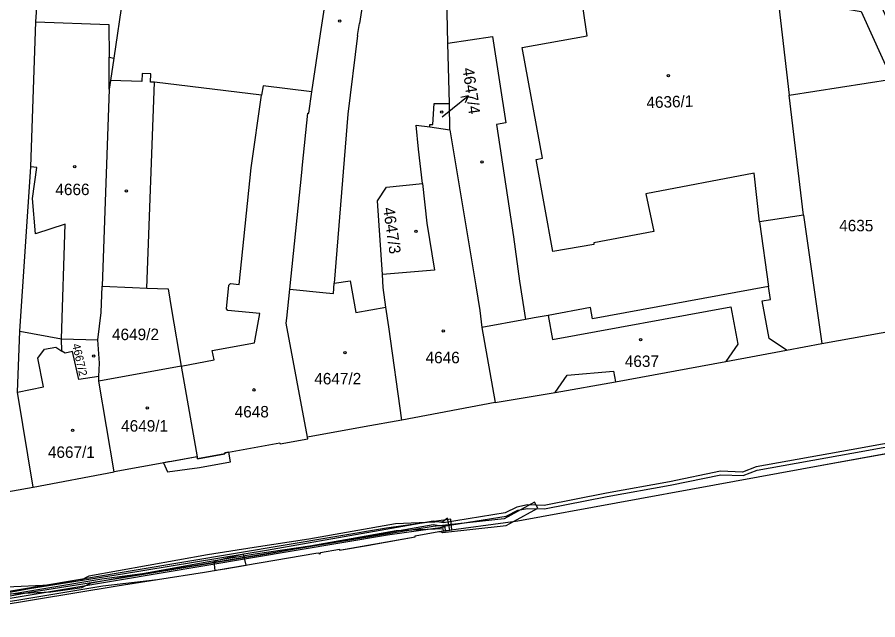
# Model space of a CAD drawing. Extents: x -756746 to -753363, y -1166406 to -1161727.
# Drawn here: x -755379 to -755251.5, y -1166104 to -1166014.7 of the extents above; entities that cross this region are included whole.
import ezdxf

# ---------------------------------------------------------------- set-up
doc = ezdxf.new("R2010")
doc.units = 0
for name, color, linetype in [('Hranice kat_území', 7, 'Continuous'), ('Hranice parcel', 7, 'Continuous'), ('Parcelní čísla', 7, 'Continuous'), ('Pop  PČ popisy', 7, 'Continuous'), ('Vnitřní kresba', 7, 'Continuous'), ('Věcná břemena k části', 7, 'Continuous'), ('Značky budov', 7, 'Continuous')]:
    doc.layers.add(name, color=color, linetype=linetype)

msp = doc.modelspace()

# ---------------------------------------------------------------- linework, layer by layer
at = {"layer": 'Hranice kat_území'}
for points in [[(-755316.54, -1166090.97), (-755304.83, -1166089.37), (-755275.71, -1166084.03), (-755259.8, -1166081.14), (-755244.88, -1166078.42)], [(-755388.47, -1166103.01), (-755364.24, -1166099.02), (-755358.23, -1166098.07), (-755351.29, -1166096.97), (-755334.76, -1166094.17), (-755334.32, -1166094.1), (-755334.29, -1166094.25), (-755334.07, -1166094.23), (-755334.1, -1166094.06), (-755331.29, -1166093.57), (-755331.26, -1166093.72), (-755320.05, -1166091.75), (-755320.08, -1166091.59), (-755316.54, -1166090.97)]]:
    msp.add_lwpolyline(points, dxfattribs=at)
at = {"layer": 'Hranice parcel'}
for p, q in [((-755376.29, -1166015.44), (-755374.69, -1165994.77)), ((-755267.71, -1165999.92), (-755264.63, -1166026.3)), ((-755364.7, -1166020.81), (-755365.2, -1166024.14)), ((-755264.63, -1166026.3), (-755249.46, -1166023.94)), ((-755262.54, -1166044.1), (-755264.63, -1166026.3)), ((-755314.91, -1166031.43), (-755315, -1166027.54)), ((-755317.9, -1166031.01), (-755314.91, -1166031.43)), ((-755262.54, -1166044.1), (-755259.81, -1166063.09)), ((-755310.49, -1166058.19), (-755310.21, -1166060.74)), ((-755303.71, -1166059.54), (-755310.21, -1166060.74)), ((-755302.45, -1166059.31), (-755303.71, -1166059.54)), ((-755259.81, -1166063.09), (-755244.79, -1166060.36)), ((-755378.64, -1166061.27), (-755372.49, -1166062.39)), ((-755310.21, -1166060.74), (-755308.23, -1166071.84)), ((-755372.49, -1166062.39), (-755367.07, -1166062.57)), ((-755354.75, -1166066.43), (-755366.95, -1166068.66)), ((-755354.75, -1166066.43), (-755352.38, -1166079.89)), ((-755366.95, -1166068.66), (-755366.93, -1166067.96)), ((-755364.64, -1166082.11), (-755366.95, -1166068.66)), ((-755308.23, -1166071.84), (-755322.06, -1166074.47)), ((-755259.8, -1166081.14), (-755244.88, -1166078.42)), ((-755352.38, -1166079.89), (-755364.64, -1166082.11)), ((-755376.64, -1166084.36), (-755364.64, -1166082.11)), ((-755275.71, -1166084.03), (-755259.8, -1166081.14)), ((-755392.01, -1166087.13), (-755376.64, -1166084.36)), ((-755304.83, -1166089.37), (-755275.71, -1166084.03)), ((-755316.54, -1166090.97), (-755304.83, -1166089.37)), ((-755351.29, -1166096.97), (-755334.76, -1166094.17))]:
    msp.add_line(p, q, dxfattribs=at)
for points in [[(-755335.36, -1166025.81), (-755334.11, -1166017.2), (-755332.76, -1166008.51), (-755330.85, -1165995.94), (-755330.23, -1165991.73), (-755328.39, -1165979.53), (-755327.36, -1165972.71)], [(-755315, -1166027.54), (-755315.21, -1166018.6), (-755315.42, -1166009.49), (-755315.47, -1166007.43), (-755315.72, -1165997.02), (-755315.75, -1165995.05), (-755306.6, -1165993.33), (-755308.94, -1165983.12), (-755310.67, -1165975.6)], [(-755361.23, -1165997.07), (-755362.04, -1166002.59), (-755364.7, -1166020.81)], [(-755378.64, -1166061.27), (-755377.01, -1166036.91), (-755376.29, -1166015.44)], [(-755376.29, -1166015.44), (-755365.45, -1166015.81), (-755365.42, -1166020.68), (-755364.7, -1166020.81)], [(-755335.36, -1166025.81), (-755342.61, -1166024.93), (-755342.81, -1166026.32), (-755358.69, -1166024.37), (-755359.27, -1166024.36), (-755359.21, -1166023.15), (-755360.51, -1166023.11), (-755360.54, -1166024.28), (-755365.2, -1166024.14)], [(-755365.2, -1166024.14), (-755365.4, -1166025.43), (-755366.45, -1166054.62)], [(-755338.64, -1166055.02), (-755336.86, -1166037.74), (-755336.74, -1166036.6), (-755335.98, -1166028.96), (-755335.84, -1166028.97), (-755335.36, -1166025.81)], [(-755317.9, -1166031.01), (-755317.87, -1166030.62), (-755317.43, -1166030.66), (-755317.23, -1166027.54), (-755315, -1166027.54)], [(-755318.99, -1166039.38), (-755319.56, -1166034.29), (-755319.92, -1166030.73), (-755317.9, -1166031.01)], [(-755314.91, -1166031.43), (-755311.1, -1166054.53), (-755310.49, -1166058.19)], [(-755324.89, -1166052.87), (-755325.63, -1166041.94), (-755324.31, -1166039.94), (-755318.99, -1166039.38)], [(-755318.99, -1166039.38), (-755318.33, -1166045.25), (-755317.18, -1166052.24), (-755324.89, -1166052.87)], [(-755262.54, -1166044.1), (-755269.04, -1166045.06), (-755267.7, -1166054.66), (-755293.79, -1166059.45), (-755294.1, -1166057.78), (-755300.35, -1166058.93), (-755302.45, -1166059.31)], [(-755338.64, -1166055.02), (-755333.27, -1166055.57), (-755332.17, -1166055.68), (-755332.05, -1166054.15), (-755329.71, -1166053.79), (-755328.86, -1166058.5), (-755324.39, -1166057.69)], [(-755324.39, -1166057.69), (-755324.79, -1166054.81), (-755324.89, -1166052.87)], [(-755367.07, -1166062.57), (-755366.59, -1166058.51), (-755366.45, -1166054.62)], [(-755366.45, -1166054.62), (-755361.96, -1166054.8), (-755359.81, -1166054.89), (-755356.68, -1166054.98), (-755356.17, -1166058.04), (-755354.75, -1166066.43)], [(-755336.04, -1166076.96), (-755339.16, -1166060.06), (-755339.09, -1166059.35), (-755338.64, -1166055.02)], [(-755322.06, -1166074.47), (-755323.98, -1166060.62), (-755324.39, -1166057.69)], [(-755376.64, -1166084.36), (-755378.98, -1166070.3), (-755378.64, -1166061.27)], [(-755366.93, -1166067.96), (-755369.9, -1166068.45), (-755370.82, -1166064.28), (-755371.91, -1166064.52), (-755372.43, -1166064.21), (-755372.49, -1166062.39)], [(-755366.93, -1166067.96), (-755366.86, -1166065.99), (-755367.07, -1166062.57)], [(-755308.23, -1166071.84), (-755299.31, -1166070.35), (-755290.38, -1166068.76), (-755274.05, -1166065.75), (-755265.05, -1166064.1), (-755259.81, -1166063.09)], [(-755322.06, -1166074.47), (-755327.61, -1166075.46), (-755336.04, -1166076.96)], [(-755352.38, -1166079.89), (-755352.33, -1166080.18), (-755348.27, -1166079.45), (-755348.29, -1166079.3), (-755340.1, -1166077.83), (-755340.08, -1166077.96), (-755335.99, -1166077.23), (-755336.04, -1166076.96)], [(-755334.76, -1166094.17), (-755334.32, -1166094.1), (-755334.29, -1166094.25), (-755334.07, -1166094.23), (-755334.1, -1166094.06), (-755331.29, -1166093.57), (-755331.26, -1166093.72), (-755320.05, -1166091.75), (-755320.08, -1166091.59), (-755316.54, -1166090.97)], [(-755364.24, -1166099.02), (-755358.23, -1166098.07), (-755351.29, -1166096.97)], [(-755395, -1166104.03), (-755388.47, -1166103.01), (-755364.24, -1166099.02)]]:
    msp.add_lwpolyline(points, dxfattribs=at)
at = {"layer": 'Pop  PČ popisy'}
for p, q in [((-755314.55, -1166028.29), (-755312.22, -1166026.4)), ((-755312.22, -1166026.4), (-755313.31, -1166026.64)), ((-755312.22, -1166026.4), (-755312.68, -1166027.42)), ((-755316.08, -1166029.52), (-755314.55, -1166028.29))]:
    msp.add_line(p, q, dxfattribs=at)
at = {"layer": 'Vnitřní kresba'}
for p, q in [((-755323.87, -1165987.08), (-755328.33, -1166015.66)), ((-755294.57, -1166017.52), (-755295.44, -1166011.5)), ((-755328.61, -1166017.48), (-755328.33, -1166015.66)), ((-755328.61, -1166017.48), (-755330.03, -1166029.11)), ((-755304.21, -1166019.25), (-755294.57, -1166017.52)), ((-755301.18, -1166035.65), (-755304.21, -1166019.25)), ((-755365.4, -1166025.43), (-755365.42, -1166020.68)), ((-755359.81, -1166054.89), (-755358.69, -1166024.37)), ((-755344.36, -1166037.06), (-755342.81, -1166026.32)), ((-755330.03, -1166029.11), (-755332.05, -1166054.15)), ((-755302.14, -1166035.84), (-755301.18, -1166035.65)), ((-755299.69, -1166049.45), (-755302.14, -1166035.84)), ((-755376.13, -1166037), (-755377.01, -1166036.91)), ((-755376.75, -1166041.62), (-755376.13, -1166037)), ((-755346.13, -1166054.35), (-755344.36, -1166037.06)), ((-755269.86, -1166037.87), (-755285.88, -1166040.94)), ((-755269.04, -1166045.06), (-755269.86, -1166037.87)), ((-755285.88, -1166040.94), (-755284.69, -1166046.51)), ((-755376.3, -1166046.83), (-755376.75, -1166041.62)), ((-755371.92, -1166045.42), (-755376.3, -1166046.83)), ((-755372.49, -1166062.39), (-755371.92, -1166045.42)), ((-755284.69, -1166046.51), (-755293.61, -1166048.19)), ((-755293.57, -1166048.4), (-755299.69, -1166049.45)), ((-755293.61, -1166048.19), (-755293.57, -1166048.4)), ((-755348.01, -1166057.94), (-755347.65, -1166054.44)), ((-755347.65, -1166054.44), (-755347.42, -1166054.22)), ((-755347.42, -1166054.22), (-755346.13, -1166054.35)), ((-755267.44, -1166056.57), (-755267.7, -1166054.66)), ((-755268.63, -1166056.79), (-755267.44, -1166056.57)), ((-755347.84, -1166058.19), (-755348.01, -1166057.94)), ((-755299.7, -1166062.5), (-755273.3, -1166057.65)), ((-755273.3, -1166057.65), (-755272.28, -1166063.19)), ((-755267.61, -1166062.33), (-755268.63, -1166056.79)), ((-755343.09, -1166058.65), (-755347.84, -1166058.19)), ((-755343.85, -1166062.98), (-755343.09, -1166058.65)), ((-755300.35, -1166058.93), (-755299.7, -1166062.5)), ((-755350.14, -1166064.15), (-755343.85, -1166062.98)), ((-755265.05, -1166064.1), (-755267.61, -1166062.33)), ((-755375.99, -1166065.29), (-755374.97, -1166063.91)), ((-755374.97, -1166063.91), (-755373.32, -1166063.65)), ((-755373.32, -1166063.65), (-755372.43, -1166064.21)), ((-755349.86, -1166065.49), (-755350.14, -1166064.15)), ((-755272.28, -1166063.19), (-755274.05, -1166065.75)), ((-755375.14, -1166069.52), (-755375.99, -1166065.29)), ((-755354.75, -1166066.43), (-755349.86, -1166065.49)), ((-755299.31, -1166070.35), (-755297.53, -1166067.8)), ((-755297.53, -1166067.8), (-755290.66, -1166067.21)), ((-755290.66, -1166067.21), (-755290.38, -1166068.76)), ((-755378.98, -1166070.3), (-755375.14, -1166069.52))]:
    msp.add_line(p, q, dxfattribs=at)
for points in [[(-755315.21, -1166018.6), (-755308.63, -1166017.62), (-755306.63, -1166030.42), (-755308.02, -1166030.63), (-755305.48, -1166047.31)], [(-755305.48, -1166047.31), (-755304.63, -1166053.88), (-755303.71, -1166059.54)]]:
    msp.add_lwpolyline(points, dxfattribs=at)
at = {"layer": 'Věcná břemena k části'}
for points in [[(-755267.91, -1165942.05), (-755261.22, -1165902.73), (-755263.19, -1165902.43), (-755269.89, -1165941.75), (-755269.98, -1165942.3), (-755271.07, -1165957.36), (-755262.8, -1165995.81), (-755261.3, -1165999.08), (-755261.41, -1165999.55), (-755262.47, -1166004.18), (-755259.32, -1166011.48), (-755255.99, -1166013.56), (-755253.98, -1166013.91), (-755249.46, -1166023.94), (-755246.26, -1166023.44), (-755247.54, -1166020.64), (-755256.71, -1166000.59), (-755258.05, -1165999.36), (-755259.65, -1165997.88), (-755260.89, -1165995.17), (-755269.06, -1165957.22), (-755267.99, -1165942.54)], [(-755347.69, -1166079.19), (-755348.29, -1166079.3), (-755348.27, -1166079.45), (-755352.33, -1166080.18), (-755352.38, -1166079.89), (-755356.11, -1166080.56), (-755356.6, -1166080.65), (-755357.37, -1166080.79), (-755356.78, -1166082.11), (-755352.02, -1166081.49), (-755347.41, -1166080.65)], [(-755349.73, -1166096.71), (-755349.24, -1166096.62), (-755348.25, -1166096.46), (-755345.1, -1166095.92), (-755345.48, -1166094.33), (-755349.89, -1166095.4)]]:
    msp.add_lwpolyline(points, close=True, dxfattribs=at)
for points in [[(-755236.37, -1166075.38), (-755255.45, -1166078.83), (-755269.55, -1166081.37), (-755271.54, -1166082.17), (-755274.81, -1166082.03), (-755282.39, -1166083.58), (-755291.72, -1166085.25), (-755300.95, -1166087.11), (-755303.44, -1166087.02), (-755305.01, -1166087.32), (-755306.75, -1166088.18), (-755315.86, -1166089.67), (-755317.39, -1166089.4), (-755342.1, -1166093.75), (-755363.41, -1166097.28), (-755377.22, -1166099.45), (-755384.22, -1166100.73)], [(-755236.37, -1166075.38), (-755255.45, -1166078.83), (-755269.55, -1166081.37), (-755271.54, -1166082.17), (-755274.81, -1166082.03), (-755282.39, -1166083.58), (-755291.72, -1166085.25), (-755300.95, -1166087.11), (-755303.44, -1166087.02), (-755305.01, -1166087.32), (-755306.75, -1166088.18), (-755315.86, -1166089.67), (-755317.39, -1166089.4), (-755342.1, -1166093.75), (-755363.41, -1166097.28), (-755377.22, -1166099.45), (-755384.22, -1166100.73)], [(-755384.1, -1166101.21), (-755377.14, -1166099.95), (-755363.33, -1166097.78), (-755342.02, -1166094.25), (-755317.39, -1166089.9), (-755315.86, -1166090.17), (-755306.59, -1166088.66), (-755304.85, -1166087.8), (-755303.4, -1166087.52), (-755300.91, -1166087.61), (-755291.62, -1166085.75), (-755282.29, -1166084.08), (-755274.77, -1166082.53), (-755271.46, -1166082.67), (-755269.41, -1166081.85), (-755255.37, -1166079.33), (-755236.27, -1166075.88)], [(-755384.1, -1166101.21), (-755377.14, -1166099.95), (-755363.33, -1166097.78), (-755342.02, -1166094.25), (-755317.39, -1166089.9), (-755315.86, -1166090.17), (-755306.59, -1166088.66), (-755304.85, -1166087.8), (-755303.4, -1166087.52), (-755300.91, -1166087.61), (-755291.62, -1166085.75), (-755282.29, -1166084.08), (-755274.77, -1166082.53), (-755271.46, -1166082.67), (-755269.41, -1166081.85), (-755255.37, -1166079.33), (-755236.27, -1166075.88)], [(-755390.05, -1166102.78), (-755378.79, -1166101.06), (-755366.34, -1166099.01), (-755358.23, -1166098.07), (-755351.29, -1166096.97), (-755334.76, -1166094.17), (-755334.32, -1166094.1), (-755334.29, -1166094.25), (-755334.07, -1166094.23), (-755334.1, -1166094.06), (-755331.29, -1166093.57), (-755331.26, -1166093.72), (-755326.88, -1166092.95), (-755326.38, -1166092.86), (-755320.05, -1166091.75), (-755320.08, -1166091.59), (-755316.54, -1166090.97), (-755316.36, -1166090.97), (-755316.18, -1166091.02), (-755316.02, -1166091.11), (-755306.56, -1166090.04), (-755305.51, -1166089.46), (-755301.89, -1166087.49), (-755302.37, -1166086.61), (-755306.86, -1166089.06), (-755317.4, -1166090.21), (-755328.55, -1166092.03), (-755358.6, -1166096.98), (-755366.48, -1166098.03), (-755378.95, -1166100.08), (-755393.52, -1166102.3)], [(-755384.8, -1166101.6), (-755324.15, -1166091.45), (-755315.69, -1166090.28), (-755315.63, -1166090.85), (-755314.64, -1166090.71), (-755314.8, -1166089.14), (-755324.31, -1166090.47), (-755384.12, -1166100.48)], [(-755380.14, -1166100.18), (-755374.03, -1166099.91), (-755369.43, -1166099.24), (-755368.09, -1166098.54), (-755350.66, -1166095.37), (-755343.75, -1166094.28), (-755335.65, -1166093.08), (-755322.9, -1166090.81), (-755315.98, -1166090.5), (-755315.9, -1166090.88), (-755314.91, -1166090.75), (-755315.27, -1166088.98), (-755315.95, -1166089.5), (-755323, -1166089.81), (-755335.81, -1166092.1), (-755343.91, -1166093.3), (-755350.82, -1166094.39), (-755368.41, -1166097.58), (-755369.75, -1166098.28), (-755374.13, -1166098.91), (-755380.63, -1166099.2)]]:
    msp.add_lwpolyline(points, dxfattribs=at)
at = {"layer": 'Značky budov'}
for centre in [(-755331.23, -1166015.32), (-755282.54, -1166023.4), (-755316.12, -1166028.8), (-755310.15, -1166036.2), (-755370.51, -1166036.9), (-755362.86, -1166040.48), (-755319.95, -1166046.47), (-755315.9, -1166061.23), (-755286.66, -1166062.51), (-755330.47, -1166064.47), (-755367.7, -1166064.96), (-755343.95, -1166069.96), (-755359.77, -1166072.64), (-755370.82, -1166075.94)]:
    msp.add_circle(centre, 0.175, dxfattribs=at)

# ---------------------------------------------------------------- texts
at = {"layer": 'Parcelní čísla'}
for s, height, rotation, p in [('4647/4', 1.7, 278, (-755313.05, -1166022.34)), ('4636/1', 1.7, 2, (-755285.77, -1166028.25)), ('4647/3', 1.7, 278, (-755324.82, -1166043.03)), ('4667/2', 1.2, 283, (-755370.89, -1166063.25))]:
    msp.add_text(s, height=height, rotation=rotation, dxfattribs=at).set_placement(p)
for s, p in [('4666', (-755373.37, -1166041.11)), ('4635', (-755257.24, -1166046.47)), ('4649/2', (-755364.98, -1166062.59)), ('4646', (-755318.52, -1166066.02)), ('4637', (-755289, -1166066.57)), ('4647/2', (-755335.01, -1166069.15)), ('4648', (-755346.8, -1166074.05)), ('4649/1', (-755363.63, -1166076.15)), ('4667/1', (-755374.48, -1166080.04))]:
    msp.add_text(s, height=1.7, dxfattribs=at).set_placement(p)

doc.saveas('drawing.dxf')
